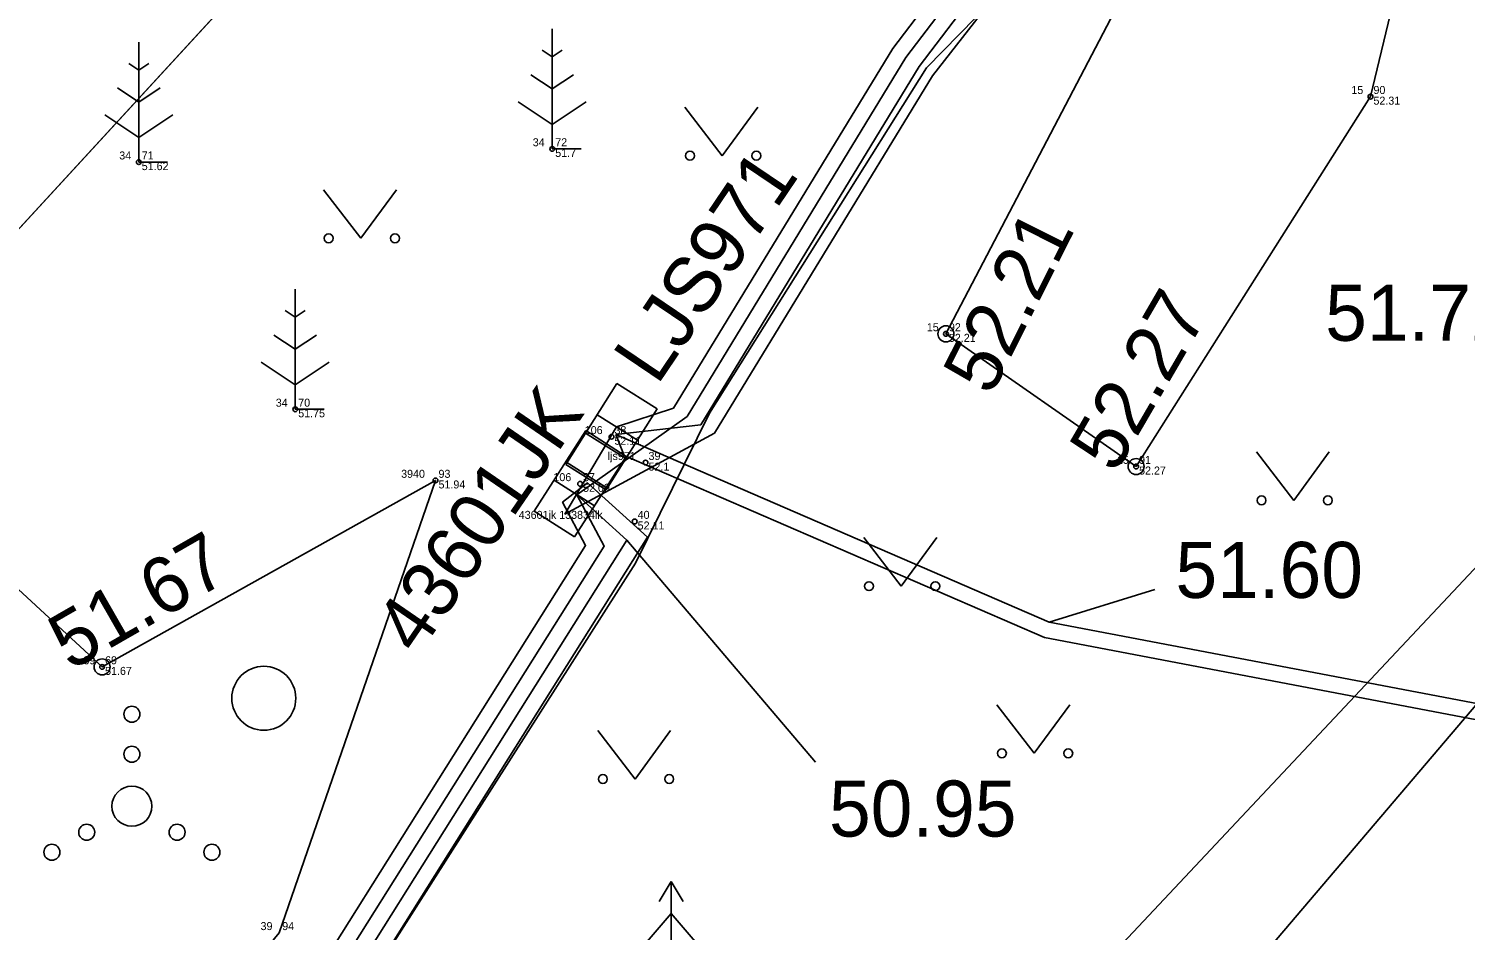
# Model space of a CAD drawing. Extents: x 543497 to 552146, y 6567125 to 6579845.
# Drawn here: x 546496.42 to 546514.37, y 6577819.96 to 6577831.22 of the extents above; entities that cross this region are included whole.
import ezdxf

# ---------------------------------------------------------------- set-up
doc = ezdxf.new("R2010")
doc.units = 0
for name, color, linetype in [('xref_Kangru tee 1_geodeesia$0$ABIJOONIS', 7, 'Continuous'), ('xref_Kangru tee 1_geodeesia$0$AED', 7, 'Continuous'), ('xref_Kangru tee 1_geodeesia$0$ELRAJATISMA', 7, 'Continuous'), ('xref_Kangru tee 1_geodeesia$0$ELRAJATISMP', 7, 'Continuous'), ('xref_Kangru tee 1_geodeesia$0$HALJASTUS', 7, 'Continuous'), ('xref_Kangru tee 1_geodeesia$0$korgus-EH2000', 7, 'Continuous'), ('xref_Kangru tee 1_geodeesia$0$mootkood', 7, 'Continuous'), ('xref_Kangru tee 1_geodeesia$0$MOOTKORG-eh2000', 7, 'Continuous'), ('xref_Kangru tee 1_geodeesia$0$mootmpunkt', 7, 'Continuous'), ('xref_Kangru tee 1_geodeesia$0$MOOTNR', 7, 'Continuous'), ('xref_Kangru tee 1_geodeesia$0$MPKAABEL', 7, 'Continuous'), ('xref_Kangru tee 1_geodeesia$0$PIIR', 7, 'Continuous'), ('xref_Kangru tee 1_geodeesia$0$PUU', 7, 'Continuous'), ('xref_Kangru tee 1_geodeesia$0$SITRASS', 7, 'Continuous'), ('xref_Kangru tee 1_geodeesia$0$TEE', 7, 'Continuous')]:
    doc.layers.add(name, color=color, linetype=linetype)

# ---------------------------------------------------------------- blocks, each defined once
blk = doc.blocks.new('xref_Kangru tee 1_geodeesia$0$KUUSK1')
for p, q in [((0, 3), (-0.3, 2.5)), ((0.3, 2.5), (0, 3)), ((0, 3), (0, 0)), ((0, 2.2), (-0.6, 1.5)), ((0.6, 1.5), (0, 2.2)), ((0, 1.3), (-0.8, 0.5)), ((0.8, 0.5), (0, 1.3)), ((0.72, 0), (0, 0))]:
    blk.add_line(p, q)
blk = doc.blocks.new('xref_Kangru tee 1_geodeesia$0$mand1')
for p, q in [((0, 3), (0, 0)), ((0, 2.3), (-0.249, 2.466)), ((0.249, 2.466), (0, 2.3)), ((0, 1.5), (-0.533, 1.855)), ((0.533, 1.855), (0, 1.5)), ((-0.849, 1.179), (0, 0.613)), ((0, 0.613), (0.849, 1.179)), ((0.72, 0), (0, 0))]:
    blk.add_line(p, q)
blk = doc.blocks.new('xref_Kangru tee 1_geodeesia$0$VQSA')
for centre, radius in [((0, 2.3), 0.2), ((0, 1.3), 0.2), ((0, 0), 0.5), ((-1.13, -0.65), 0.2), ((1.13, -0.65), 0.2), ((-2, -1.15), 0.2), ((2, -1.15), 0.2)]:
    blk.add_circle(centre, radius)
blk = doc.blocks.new('xref_Kangru tee 1_geodeesia$0$METS')
blk.add_circle((0, 0), 0.8)
blk = doc.blocks.new('xref_Kangru tee 1_geodeesia$0$MURU')
for p, q in [((-0.927, 1.213), (0, 0)), ((0, 0), (0.891, 1.213))]:
    blk.add_line(p, q)
for centre in [(-0.802, 0), (0.856, 0)]:
    blk.add_circle(centre, 0.11)
blk = doc.blocks.new('xref_Kangru tee 1_geodeesia$0$ELKAPP')
for p, q in [((1.195, 0.597), (-1.195, 0.597)), ((-1.195, 0.597), (-1.195, -0.597)), ((-0.271, 0.597), (-0.271, -0.597)), ((0.271, 0.597), (0.271, -0.597)), ((1.195, -0.597), (1.195, 0.597)), ((-1.195, -0.597), (1.195, -0.597))]:
    blk.add_line(p, q)

msp = doc.modelspace()

# ---------------------------------------------------------------- linework, layer by layer
at = {"layer": 'xref_Kangru tee 1_geodeesia$0$ABIJOONIS'}
for points in [[(546506.253, 6577822.056), (546503.897, 6577824.832)], [(546509.176, 6577823.808), (546510.493, 6577824.217)]]:
    msp.add_lwpolyline(points, dxfattribs=at)
at = {"layer": 'xref_Kangru tee 1_geodeesia$0$AED'}
msp.add_lwpolyline([(546374.31, 6577786.287), (546384.887, 6577789.146), (546399.733, 6577793.174), (546403.81, 6577794.256), (546421.667, 6577798.052), (546437.665, 6577801.447), (546455.818, 6577805.013), (546463.114, 6577806.4), (546469.74, 6577807.752), (546486.105, 6577811.115), (546490.622, 6577812.093), (546508.552, 6577816.489), (546510.491, 6577818.05), (546517.026, 6577825.733)], dxfattribs=at)
at = {"layer": 'xref_Kangru tee 1_geodeesia$0$ELRAJATISMA'}
for points in [[(546504.478, 6577826.48), (546507.219, 6577830.975), (546508.665, 6577832.879), (546512.696, 6577836.397), (546513.022, 6577835.886), (546509.246, 6577832.59), (546507.715, 6577830.636), (546504.991, 6577826.168), (546503.121, 6577825.158), (546503.766, 6577826.25), (546504.478, 6577826.48)], [(546497.861, 6577815.985), (546503.381, 6577824.765), (546503.093, 6577825.305), (546503.403, 6577825.547), (546504.156, 6577824.868), (546498.382, 6577815.686), (546497.861, 6577815.985)]]:
    msp.add_lwpolyline(points, dxfattribs=at)
at = {"layer": 'xref_Kangru tee 1_geodeesia$0$HALJASTUS'}
msp.add_lwpolyline([(546487.184, 6577820.857), (546488.395, 6577820.418), (546494.459, 6577825.906), (546497.338, 6577823.248), (546501.505, 6577825.578), (546499.552, 6577819.926), (546496.026, 6577815.641), (546488.056, 6577812.337), (546480.928, 6577810.907), (546480.465, 6577813.255), (546483.503, 6577812.976)], dxfattribs=at)
at = {"layer": 'xref_Kangru tee 1_geodeesia$0$korgus-EH2000'}
for centre in [(546507.884, 6577827.41), (546510.261, 6577825.752), (546497.338, 6577823.248)]:
    msp.add_circle(centre, 0.1, dxfattribs=at)
at = {"layer": 'xref_Kangru tee 1_geodeesia$0$mootmpunkt'}
for centre in [(546513.19, 6577830.374), (546502.964, 6577829.721), (546497.796, 6577829.556), (546507.884, 6577827.41), (546499.752, 6577826.467), (546503.704, 6577826.124), (546504.13, 6577825.801), (546510.261, 6577825.752), (546501.505, 6577825.578), (546503.312, 6577825.536), (546503.994, 6577825.065), (546497.338, 6577823.248)]:
    msp.add_circle(centre, 0.03, dxfattribs=at)
at = {"layer": 'xref_Kangru tee 1_geodeesia$0$MPKAABEL'}
for points in [[(546527.321, 6577847.419), (546527.372, 6577846.687), (546525.769, 6577845.343), (546514.748, 6577837.09), (546512.804, 6577836.227), (546508.812, 6577832.742), (546507.384, 6577830.862), (546504.649, 6577826.376), (546503.269, 6577825.399)], [(546503.758, 6577826.154), (546504.82, 6577826.272), (546507.549, 6577830.749), (546508.959, 6577832.605), (546512.913, 6577836.056), (546514.85, 6577836.916), (546525.893, 6577845.186), (546527.457, 6577846.497), (546527.52, 6577846.865)], [(546503.758, 6577826.154), (546509.176, 6577823.808), (546514.54, 6577822.788), (546514.842, 6577822.992), (546515.349, 6577825.341), (546516.271, 6577826.463), (546517.974, 6577827.442), (546522.541, 6577828.279), (546525.336, 6577829.066), (546526.388, 6577828.715), (546528.158, 6577828.125)], [(546503.758, 6577826.154), (546503.862, 6577825.891), (546509.117, 6577823.616), (546514.584, 6577822.576), (546515.021, 6577822.871), (546515.534, 6577825.251), (546516.402, 6577826.308), (546518.044, 6577827.251), (546522.586, 6577828.084), (546525.025, 6577828.771)], [(546503.269, 6577825.399), (546503.897, 6577824.832), (546498.209, 6577815.786), (546496.753, 6577812.99), (546489.709, 6577811.384), (546480.649, 6577809.527), (546472.536, 6577807.713), (546463.953, 6577805.953), (546454.561, 6577804.305), (546451.773, 6577803.734), (546450.066, 6577804.71), (546449.042, 6577804.761), (546443.032, 6577803.531), (546441.007, 6577803.08), (546435.104, 6577801.993), (546428.129, 6577800.42), (546417.49, 6577798.156), (546402.596, 6577794.957), (546396.256, 6577793.425), (546392.119, 6577794.514)], [(546503.269, 6577825.399), (546503.613, 6577824.757), (546498.035, 6577815.885), (546496.619, 6577813.164), (546489.667, 6577811.58), (546480.607, 6577809.722), (546472.494, 6577807.909), (546463.915, 6577806.15), (546454.523, 6577804.501), (546451.806, 6577803.945), (546450.124, 6577804.907), (546449.027, 6577804.962), (546442.991, 6577803.727), (546440.662, 6577805.138)]]:
    msp.add_lwpolyline(points, dxfattribs=at)
at = {"layer": 'xref_Kangru tee 1_geodeesia$0$PIIR'}
for points in [[(546455.94, 6577805.47), (546452.89, 6577819.28), (546448.94, 6577824.49), (546483.99, 6577862.81), (546484.68, 6577863.57), (546508.03, 6577841.48), (546479.51, 6577810.47), (546455.94, 6577805.47)], [(546117.94, 6577707.48), (546328.8, 6577761.79), (546320.77, 6577750.51), (546433.24, 6577777.18), (546446.51, 6577792.1), (546464.1, 6577793.71), (546479.51, 6577810.47), (546508.03, 6577841.48)]]:
    msp.add_lwpolyline(points, dxfattribs=at)
at = {"layer": 'xref_Kangru tee 1_geodeesia$0$PUU'}
msp.add_lwpolyline([(546515.061, 6577825.08), (546508.999, 6577818.629), (546506.695, 6577817.409)], dxfattribs=at)
at = {"layer": 'xref_Kangru tee 1_geodeesia$0$SITRASS'}
msp.add_lwpolyline([(546441.003, 6577802.952), (546448.938, 6577804.593), (546449.988, 6577804.587), (546452.008, 6577803.679), (546454.595, 6577804.108), (546463.99, 6577805.757), (546472.578, 6577807.518), (546480.691, 6577809.331), (546489.752, 6577811.189), (546496.891, 6577812.816), (546497.942, 6577815.038), (546504.004, 6577824.544), (546504.927, 6577826.417), (546507.64, 6577830.733), (546508.664, 6577831.785), (546509.333, 6577831.789)], dxfattribs=at)
at = {"layer": 'xref_Kangru tee 1_geodeesia$0$TEE'}
msp.add_lwpolyline([(546513.833, 6577842.073), (546514.731, 6577836.776), (546513.19, 6577830.374), (546510.261, 6577825.752), (546507.884, 6577827.41), (546510.36, 6577832.15), (546512.252, 6577836.6), (546511.243, 6577841.494)], dxfattribs=at)

# ---------------------------------------------------------------- block references
at = {"layer": 'xref_Kangru tee 1_geodeesia$0$ELRAJATISMP'}
for p, xscale, yscale, rotation in [((546503.704, 6577826.124), 0.49999999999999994, 0.5, 57.83964403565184), ((546503.312, 6577825.536), 0.5, 0.49999999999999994, 57.377641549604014)]:
    msp.add_blockref('xref_Kangru tee 1_geodeesia$0$ELKAPP', p, dxfattribs=dict(at, xscale=xscale, yscale=yscale, rotation=rotation))
at = {"layer": 'xref_Kangru tee 1_geodeesia$0$HALJASTUS', "xscale": 0.5, "yscale": 0.5}
for name, p in [('xref_Kangru tee 1_geodeesia$0$MURU', (546505.086, 6577829.636)), ('xref_Kangru tee 1_geodeesia$0$MURU', (546500.57, 6577828.604)), ('xref_Kangru tee 1_geodeesia$0$MURU', (546512.23, 6577825.329)), ('xref_Kangru tee 1_geodeesia$0$MURU', (546507.323, 6577824.257)), ('xref_Kangru tee 1_geodeesia$0$METS', (546499.359, 6577822.856)), ('xref_Kangru tee 1_geodeesia$0$VQSA', (546497.71, 6577821.507)), ('xref_Kangru tee 1_geodeesia$0$MURU', (546508.985, 6577822.168)), ('xref_Kangru tee 1_geodeesia$0$MURU', (546503.998, 6577821.847))]:
    msp.add_blockref(name, p, dxfattribs=at)
at = {"layer": 'xref_Kangru tee 1_geodeesia$0$PUU', "xscale": 0.5, "yscale": 0.5}
for name, p in [('xref_Kangru tee 1_geodeesia$0$mand1', (546502.964, 6577829.721)), ('xref_Kangru tee 1_geodeesia$0$mand1', (546497.796, 6577829.556)), ('xref_Kangru tee 1_geodeesia$0$mand1', (546499.752, 6577826.467)), ('xref_Kangru tee 1_geodeesia$0$KUUSK1', (546504.451, 6577819.065))]:
    msp.add_blockref(name, p, dxfattribs=at)

# ---------------------------------------------------------------- texts
at = {"layer": 'xref_Kangru tee 1_geodeesia$0$ABIJOONIS'}
for s, p in [('51.72', (546512.624, 6577827.323)), ('51.60', (546510.753, 6577824.11)), ('50.95', (546506.423, 6577821.128))]:
    msp.add_text(s, height=0.7, dxfattribs=at).set_placement(p)
at = {"layer": 'xref_Kangru tee 1_geodeesia$0$ELRAJATISMP'}
for s, rotation, p in [('LJS971', 55.9605, (546504.276, 6577826.755)), ('43601JK', 55.5151, (546501.285, 6577823.377))]:
    msp.add_text(s, height=0.7, rotation=rotation, dxfattribs=at).set_placement(p)
at = {"layer": 'xref_Kangru tee 1_geodeesia$0$korgus-EH2000'}
for s, rotation, p in [(' 52.21 ', 63.3068, (546508.33, 6577826.388)), (' 52.27 ', 59.8219, (546509.87, 6577825.424)), (' 51.67 ', 29.8443, (546496.717, 6577823.063))]:
    msp.add_text(s, height=0.7, rotation=rotation, dxfattribs=at).set_placement(p)
at = {"layer": 'xref_Kangru tee 1_geodeesia$0$mootkood'}
for s, p in [(' 15', (546512.914, 6577830.407)), (' 34', (546502.683, 6577829.754)), (' 34', (546497.515, 6577829.589)), (' 15', (546507.608, 6577827.443)), (' 34', (546499.471, 6577826.5)), (' 106', (546503.333, 6577826.157)), (' ljs971', (546503.62, 6577825.834)), (' 15', (546509.985, 6577825.785)), (' 3940', (546501.038, 6577825.611)), (' 106', (546502.941, 6577825.569)), (' 43601jk 133834lk', (546502.508, 6577825.098)), (' 39', (546497.067, 6577823.281)), (' 39', (546499.281, 6577819.959))]:
    msp.add_text(s, height=0.1, dxfattribs=at).set_placement(p)
at = {"layer": 'xref_Kangru tee 1_geodeesia$0$MOOTKORG-eh2000'}
for s, p in [(' 52.31', (546513.19, 6577830.274)), (' 51.7', (546502.964, 6577829.621)), (' 51.62', (546497.796, 6577829.456)), (' 52.21', (546507.884, 6577827.31)), (' 51.75', (546499.752, 6577826.367)), (' 52.11', (546503.704, 6577826.024)), (' 52.1', (546504.13, 6577825.701)), (' 52.27', (546510.261, 6577825.652)), (' 51.94', (546501.505, 6577825.478)), (' 52.09', (546503.312, 6577825.436)), (' 52.11', (546503.994, 6577824.965)), (' 51.67', (546497.338, 6577823.148))]:
    msp.add_text(s, height=0.1, dxfattribs=at).set_placement(p)
at = {"layer": 'xref_Kangru tee 1_geodeesia$0$MOOTNR'}
for s, p in [(' 90', (546513.19, 6577830.407)), (' 72', (546502.964, 6577829.754)), (' 71', (546497.796, 6577829.589)), (' 92', (546507.884, 6577827.443)), (' 70', (546499.752, 6577826.5)), (' 38', (546503.704, 6577826.157)), (' 39', (546504.13, 6577825.834)), (' 91', (546510.261, 6577825.785)), (' 93', (546501.505, 6577825.611)), (' 37', (546503.312, 6577825.569)), (' 40', (546503.994, 6577825.098)), (' 69', (546497.338, 6577823.281)), (' 94', (546499.552, 6577819.959))]:
    msp.add_text(s, height=0.1, dxfattribs=at).set_placement(p)

doc.saveas('drawing.dxf')
